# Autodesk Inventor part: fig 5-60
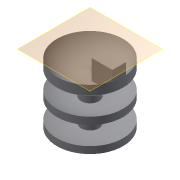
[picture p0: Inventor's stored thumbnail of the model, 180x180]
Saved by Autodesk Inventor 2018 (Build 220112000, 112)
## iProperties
Created: 2004-05
Part Number: fig 5-60
Document SubType Name: Modeling
Designer: CADCIM Technologies
Manufacturer: Standard
Standards Organization: Custom
Density: 1 g/cm^3
Material: Generic
Appearance: Default
Author: CADCIM Technologies
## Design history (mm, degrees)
sketch "Sketch1"
  geometry: L1 (0.098, 22.743)-(0.098, 0.516); L2 (-3.621, 19.305)-(-3.621, 13.061); L3 (-3.621, 10.379)-(-3.621, 3.25); L4 (-3.664, 0.516)-(0.098, 0.516); L5 (-13.694, 4.7)-(-13.694, 1.836); L6 (-13.694, 26.851)-(-13.694, 23.014); L7 (-13.694, 15.335)-(-13.694, 12.343); A1 r 10.546 centre (-4.597, 32.185) between (-13.694, 26.851) and (0.098, 22.743); A2 r 21.828 centre (-4.597, 32.185) between (-13.694, 12.343) and (-3.621, 10.379); A3 r 12.918 centre (-4.597, 32.185) between (-13.694, 23.014) and (-3.621, 19.305); A4 r 19.149 centre (-4.597, 32.185) between (-13.694, 15.335) and (-3.621, 13.061); A5 r 28.952 centre (-4.597, 32.185) between (-13.694, 4.7) and (-3.621, 3.25); A6 r 31.683 centre (-4.597, 32.185) between (-13.694, 1.836) and (-3.664, 0.516)
  constraints: 14 end point, 12 point on circle, 6 centre point, 4 perpendicular, 2 parallel, 1 vertical
revolve "Revolution1" sketch "Sketch1" stored, may be unused: angle "d0" = 90 deg
workplane "Work Plane1"
sketch "Sketch2"
  geometry: L1 (3.408, -2.846)-(12.06, -2.846); L2 (12.06, -2.846)-(12.06, 2.873); L3 (12.06, 2.873)-(3.408, 2.873); L4 (3.408, 2.873)-(3.408, -2.846)
  constraints: 8 end point, 2 parallel, 1 horizontal, 1 perpendicular
extrude "Extrusion3" join sketch "Sketch2" stored distance "d8" = 10; taper "d9" = 0 deg
body "Solid1"
